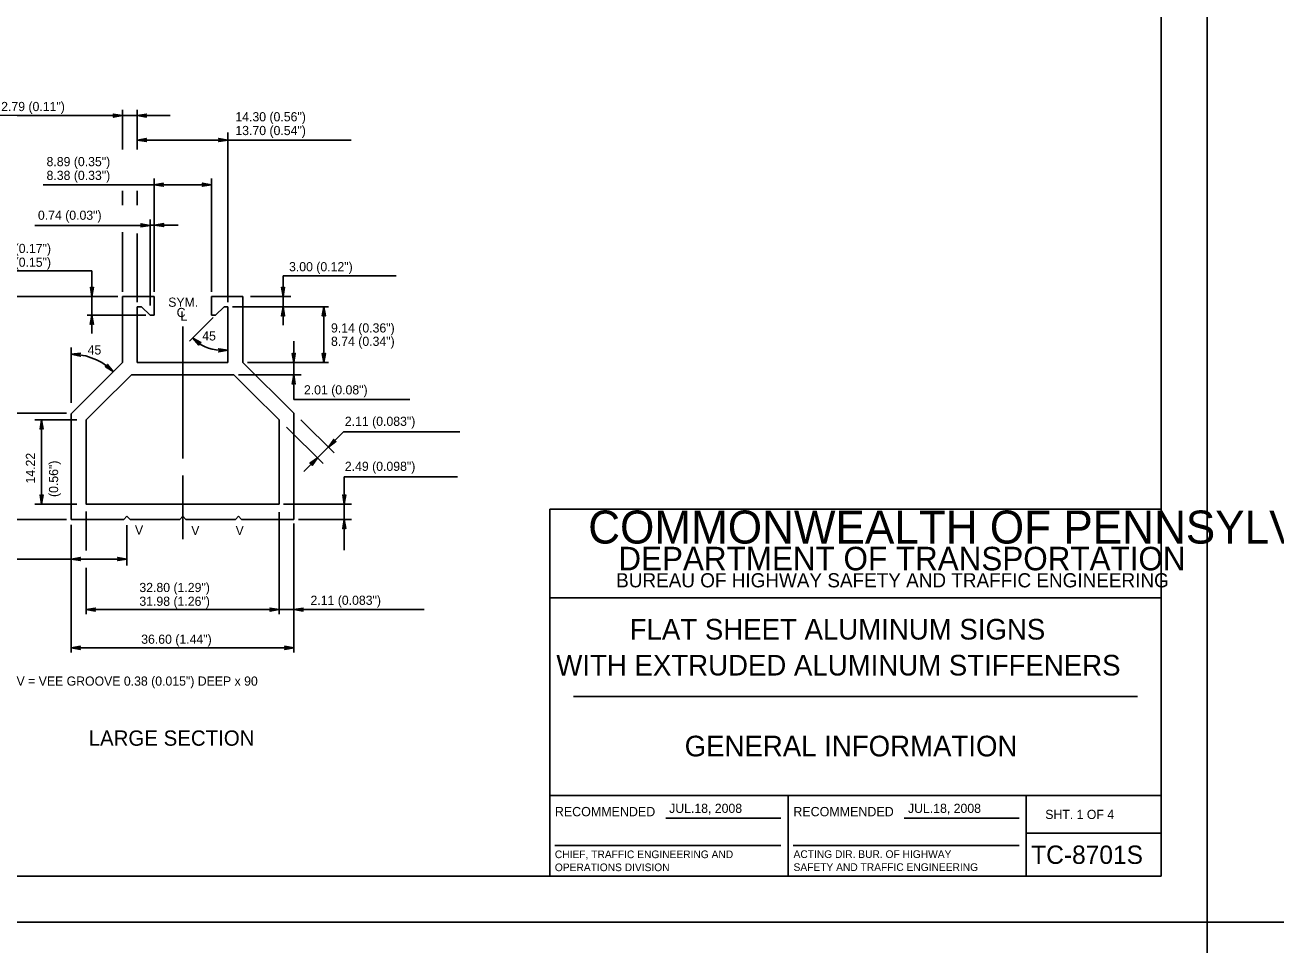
# Model space of a CAD drawing. Extents: x 650495 to 652241, y 298458 to 299646.
# Drawn here: x 650949.7 to 651358.9, y 299044.1 to 299344.9 of the extents above; entities that cross this region are included whole.
import ezdxf

# ---------------------------------------------------------------- set-up
doc = ezdxf.new("R2010")
doc.units = 0
for name, color, linetype in [('1', 7, 'Continuous'), ('2', 7, 'Continuous'), ('3', 7, 'Continuous'), ('Default', 7, 'Continuous'), ('PLT-BNDY', 7, 'Continuous')]:
    doc.layers.add(name, color=color, linetype=linetype)

# ---------------------------------------------------------------- blocks, each defined once
blk = doc.blocks.new('RARROW')
at = {"layer": '3'}
blk.add_lwpolyline([(-2.2695, 0.285), (-2.184875, 0.12075), (0, 0), (-2.2695, 0.285), (-2.38575, 0.384625), (0, 0), (-2.183125, -0.108), (-2.262875, -0.2705), (0, 0), (-2.38575, -0.379125), (-2.262875, -0.2705)], dxfattribs=at)

msp = doc.modelspace()

# ---------------------------------------------------------------- linework, layer by layer
at = {"layer": '1'}
for p, q in [((651321.31, 299066.63), (651321.31, 299630.63)), ((651121.31, 299066.63), (651121.31, 299186.63)), ((651121.31, 299186.63), (651321.31, 299186.63)), ((651321.31, 299157.63), (651121.31, 299157.63)), ((651129.06, 299125.31), (651313.56, 299125.31)), ((651121.31, 299093), (651321.31, 299093)), ((651199.31, 299093), (651199.31, 299066.63)), ((651277.19, 299066.63), (651277.19, 299093)), ((651159.24, 299085.57), (651196.87, 299085.57)), ((651237.24, 299085.57), (651274.87, 299085.57)), ((651277.19, 299080.63), (651321.31, 299080.63)), ((651122.99, 299076.68), (651196.87, 299076.68)), ((651200.99, 299076.68), (651274.87, 299076.68)), ((651321.31, 299066.63), (650535.31, 299066.63)), ((650535.31, 299066.63), (651121.31, 299066.63))]:
    msp.add_line(p, q, dxfattribs=at)
at = {"layer": '2'}
for p, q in [((650981.53, 299304.15), (650981.53, 299317.17)), ((650986.41, 299304.15), (650986.41, 299317.17)), ((650939.78, 299315.27), (650981.53, 299315.27)), ((650981.53, 299315.27), (650997.19, 299315.27)), ((651016.03, 299254.27), (651016.03, 299309.76)), ((650986.41, 299307.28), (651056.34, 299307.28)), ((650955.6, 299292.67), (651010.66, 299292.67)), ((650991.91, 299257.65), (650991.91, 299294.72)), ((651010.66, 299257.65), (651010.66, 299294.72)), ((650981.53, 299285.96), (650981.53, 299290.68)), ((650986.41, 299285.96), (650986.41, 299290.68)), ((650952.91, 299279.38), (650990.57, 299279.38)), ((650990.66, 299253.19), (650990.66, 299281.35)), ((650990.66, 299279.48), (650999.82, 299279.48)), ((650981.53, 299257.65), (650981.53, 299277.21)), ((650986.41, 299254.27), (650986.41, 299276.76)), ((650935.67, 299264.51), (650971.55, 299264.51)), ((650971.55, 299264.51), (650971.55, 299256.15)), ((651034.07, 299262.9), (651034.07, 299256.15)), ((651034.07, 299262.9), (651071.04, 299262.9)), ((650980.03, 299256.15), (650930.42, 299256.15)), ((650971.55, 299244.02), (650971.55, 299256.15)), ((650981.53, 299234.52), (650981.53, 299256.15)), ((650981.53, 299256.15), (650991.91, 299256.15)), ((650991.91, 299250.02), (650991.91, 299256.15)), ((651010.66, 299256.15), (651020.91, 299256.15)), ((651010.66, 299250.02), (651010.66, 299256.15)), ((651020.91, 299256.15), (651020.91, 299234.52)), ((651023.39, 299256.15), (651036.63, 299256.15)), ((651034.07, 299246.77), (651034.07, 299256.15)), ((650986.41, 299252.77), (650986.41, 299234.52)), ((650987.78, 299252.77), (650986.41, 299252.77)), ((650987.78, 299252.77), (650990.66, 299250.02)), ((651014.78, 299252.77), (651012.04, 299250.02)), ((651014.78, 299252.77), (651016.03, 299252.77)), ((651016.03, 299252.77), (651016.03, 299234.52)), ((651017.53, 299252.77), (651048.98, 299252.77)), ((651047.42, 299252.77), (651047.42, 299234.52)), ((650989.16, 299250.02), (650970.05, 299250.02)), ((650990.66, 299250.02), (650991.91, 299250.02)), ((651001.28, 299203.15), (651001.28, 299246.34)), ((651011.26, 299249.24), (651003.54, 299241.5)), ((651010.66, 299250.02), (651012.04, 299250.02)), ((650964.78, 299221.31), (650964.78, 299239.4)), ((651013.4, 299238.53), (651016.03, 299238.53)), ((651037.58, 299241.55), (651037.58, 299234.52)), ((650964.78, 299217.77), (650981.53, 299234.52)), ((650986.41, 299234.52), (650999.16, 299234.52)), ((651001.28, 299234.52), (651007.78, 299234.52)), ((651007.78, 299234.52), (651016.03, 299234.52)), ((651020.91, 299234.52), (651037.66, 299218.02)), ((651022.41, 299234.52), (651048.98, 299234.52)), ((651037.58, 299234.52), (651037.58, 299222.4)), ((651019.53, 299230.52), (651039.96, 299230.52)), ((651037.58, 299222.4), (651075.56, 299222.4)), ((650963.28, 299218.03), (650937.68, 299218.03)), ((650964.78, 299183.27), (650964.78, 299217.77)), ((651037.66, 299218.02), (651037.66, 299183.27)), ((650952.95, 299215.77), (650966.6, 299215.77)), ((650955.1, 299215.77), (650955.1, 299188.27)), ((651035.2, 299213.38), (651047.2, 299201.57)), ((651039.89, 299215.81), (651050.84, 299205.03)), ((651045.37, 299203.36), (651053.91, 299211.9)), ((651053.91, 299211.9), (651091.88, 299211.9)), ((651040.91, 299198.9), (651045.37, 299203.36)), ((651001.28, 299176.77), (651001.28, 299197.65)), ((651054.09, 299197.15), (651091.1, 299197.15)), ((651054.09, 299197.15), (651054.09, 299188.27)), ((650952.95, 299188.27), (650966.6, 299188.27)), ((650969.66, 299185.85), (650969.66, 299173.05)), ((651032.78, 299185.62), (651032.78, 299152.27)), ((651034.28, 299188.27), (651056.47, 299188.27)), ((651054.09, 299188.27), (651054.09, 299173.21)), ((650963.28, 299183.27), (650930.42, 299183.27)), ((650982.03, 299183.27), (650964.78, 299183.27)), ((650964.78, 299181.46), (650964.78, 299139.77)), ((650983.03, 299184.27), (650982.03, 299183.27)), ((650984.03, 299183.27), (650983.03, 299184.27)), ((650983.03, 299181.37), (650983.03, 299168.17)), ((651000.28, 299183.27), (650984.03, 299183.27)), ((651000.28, 299183.27), (651001.28, 299184.27)), ((651001.28, 299184.27), (651000.28, 299183.27)), ((651002.28, 299183.27), (651001.28, 299184.27)), ((651018.53, 299183.27), (651002.28, 299183.27)), ((651018.53, 299183.27), (651019.53, 299184.27)), ((651019.53, 299184.27), (651018.53, 299183.27)), ((651019.53, 299184.27), (651020.53, 299183.27)), ((651020.53, 299183.27), (651019.53, 299184.27)), ((651037.66, 299183.27), (651020.53, 299183.27)), ((651037.66, 299181.93), (651037.66, 299139.77)), ((651039.16, 299183.27), (651056.47, 299183.27)), ((650926.56, 299170.3), (650983.03, 299170.3)), ((650969.66, 299167.44), (650969.66, 299152.27)), ((650969.66, 299153.77), (651032.78, 299153.77)), ((651080.25, 299153.77), (651032.78, 299153.77)), ((650964.78, 299141.27), (651037.66, 299141.27))]:
    msp.add_line(p, q, dxfattribs=at)
for points in [[(650999.16, 299234.52), (651001.28, 299234.52)], [(650984.53, 299230.52), (650973.78, 299219.9)], [(650999.16, 299230.52), (650984.53, 299230.52)], [(651001.28, 299230.52), (650999.16, 299230.52)], [(651007.78, 299230.52), (651001.28, 299230.52)], [(651018.03, 299230.52), (651007.78, 299230.52)], [(651023.78, 299224.77), (651018.03, 299230.52)], [(651032.78, 299200.15), (651032.78, 299215.77), (651023.78, 299224.77)], [(650973.78, 299219.9), (650969.66, 299215.77), (650969.66, 299188.27), (650973.78, 299188.27)], [(651007.78, 299188.27), (651032.78, 299188.27), (651032.78, 299200.15)], [(650973.78, 299188.27), (651001.28, 299188.27)], [(651001.28, 299188.27), (651005.91, 299188.27)], [(651005.91, 299188.27), (651007.78, 299188.27)]]:
    msp.add_lwpolyline(points, dxfattribs=at)
for centre, radius, start, end in [((651014, 299251.58), 13.06, 223.8098, 267.3752), ((650964.78, 299217.77), 19.5, 45, 90)]:
    msp.add_arc(centre, radius, start, end, dxfattribs=at)
at = {"layer": 'PLT-BNDY'}
for points in [[(650495.31, 299645.63), (651336.31, 299645.63), (651336.31, 299051.63), (650495.31, 299051.63)], [(651336.31, 299645.63), (652177.31, 299645.63), (652177.31, 299051.63), (651336.31, 299051.63)], [(650495.31, 299051.63), (651336.31, 299051.63), (651336.31, 298457.63), (650495.31, 298457.63)], [(651336.31, 299051.63), (652177.31, 299051.63), (652177.31, 298457.63), (651336.31, 298457.63)]]:
    msp.add_lwpolyline(points, close=True, dxfattribs=at)

# ---------------------------------------------------------------- block references
at = {"layer": '2', "xscale": 1.2574347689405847, "yscale": 1.3092961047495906}
for p in [(650981.53, 299315.27), (651016.03, 299307.28), (651010.66, 299292.67), (650990.57, 299279.38), (651016.03, 299238.53), (650983.03, 299170.3), (651032.78, 299153.77), (651037.66, 299141.27)]:
    msp.add_blockref('RARROW', p, dxfattribs=at)
at = {"layer": '2'}
for p, xscale, yscale, rotation in [((650986.41, 299315.27), 1.2574347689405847, 1.3092961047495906, 180), ((650986.41, 299307.28), 1.2574347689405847, 1.3092961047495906, 180), ((650991.91, 299292.67), 1.2574347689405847, 1.3092961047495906, 180), ((650992.09, 299279.48), 1.2574347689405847, 1.3092961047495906, 180), ((650971.55, 299256.15), 1.2574347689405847, 1.3092961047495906, -90.00000000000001), ((651034.07, 299256.15), 1.2574347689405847, 1.3092961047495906, -90.00000000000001), ((651034.07, 299252.77), 1.2574347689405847, 1.3092961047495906, 89.99999999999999), ((651047.42, 299252.77), 1.2574347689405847, 1.3092961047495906, 89.99999999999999), ((650971.55, 299250.02), 1.2574347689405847, 1.3092961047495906, 89.99999999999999), ((651004.57, 299242.54), 1.2574347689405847, 1.3092961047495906, 140.9194989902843), ((650964.78, 299237.27), 1.2574347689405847, 1.3092961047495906, 176.80414646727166), ((650978.57, 299231.56), 1.2574347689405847, 1.3092961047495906, -40.89957129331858), ((651037.58, 299234.52), 1.2574347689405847, 1.3092961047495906, -90.00000000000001), ((651047.42, 299234.52), 1.2574347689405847, 1.3092961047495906, -90.00000000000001), ((651037.58, 299230.52), 1.2574347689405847, 1.3092961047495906, 89.99999999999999), ((650955.1, 299215.77), 1.2574347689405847, 1.3092961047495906, 89.99999999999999), ((651048.93, 299206.89), 1.2574347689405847, 1.3092961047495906, -134.02087905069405), ((651045.37, 299203.36), 1.2574347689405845, 1.3092961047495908, 44.7961575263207), ((650955.1, 299188.27), 1.2574347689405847, 1.3092961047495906, -90.00000000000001), ((651054.09, 299188.27), 1.2574347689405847, 1.3092961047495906, -90.00000000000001), ((651054.09, 299183.27), 1.2574347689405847, 1.3092961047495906, 89.99999999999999), ((650964.78, 299170.3), 1.2574347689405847, 1.3092961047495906, 180), ((650969.66, 299153.77), 1.2574347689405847, 1.3092961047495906, 180), ((651037.66, 299153.77), 1.2574347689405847, 1.3092961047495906, 180), ((650964.78, 299141.27), 1.2574347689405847, 1.3092961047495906, 180)]:
    msp.add_blockref('RARROW', p, dxfattribs=dict(at, xscale=xscale, yscale=yscale, rotation=rotation))

# ---------------------------------------------------------------- texts
at = {"layer": '1'}
for s, height, p in [('COMMONWEALTH OF PENNSYLVANIA', 10.7828, (651133.9, 299175.36)), ('DEPARTMENT OF TRANSPORTATION', 7.6837, (651143.76, 299166.61)), ('BUREAU OF HIGHWAY SAFETY AND TRAFFIC ENGINEERING', 4.6253, (651143.04, 299161.04)), ('FLAT SHEET ALUMINUM SIGNS', 6.75, (651147.47, 299143.97)), ('WITH EXTRUDED ALUMINUM STIFFENERS', 6.75, (651123.47, 299132.22)), ('GENERAL INFORMATION', 6.75, (651165.45, 299105.78)), ('RECOMMENDED', 3.048, (651122.99, 299086.2)), ('RECOMMENDED', 3.048, (651200.99, 299086.2)), ('SHT. 1 OF 4', 3, (651283.4, 299085.31)), ('CHIEF, TRAFFIC ENGINEERING AND', 2.5, (651122.99, 299072.51)), ('TC-8701S', 6, (651278.79, 299070.63)), ('OPERATIONS DIVISION', 2.5, (651122.99, 299068.26))]:
    msp.add_text(s, height=height, dxfattribs=at).set_placement(p)
at = {"layer": '2'}
for s, height, p in [('2.79 (0.11")', 3, (650941.89, 299316.74)), ('14.30 (0.56")', 3, (651018.49, 299313.39)), ('13.70 (0.54")', 3, (651018.49, 299308.89)), ('8.89 (0.35")', 3, (650956.73, 299298.73)), ('8.38 (0.33")', 3, (650956.73, 299294.23)), ('0.74 (0.03")', 3, (650953.91, 299281.2)), ('4.17 (0.17")', 3, (650937.37, 299270.34)), ('3.81 (0.15")', 3, (650937.37, 299265.84)), ('3.00 (0.12")', 3, (651036.04, 299264.37)), ('SYM.', 3, (650996.53, 299252.77)), ('C', 3, (650999.28, 299249.4)), ('L', 3, (651000.53, 299248.27)), ('9.14 (0.36")', 3, (651049.77, 299244.35)), ('45', 3, (651007.65, 299241.75)), ('8.74 (0.34")', 3, (651049.77, 299239.98)), ('45', 3, (650970.16, 299237.15)), ('2.01 (0.08")', 3, (651040.92, 299224.11)), ('2.11 (0.083")', 3, (651054.3, 299213.83)), ('2.49 (0.098")', 3, (651054.3, 299199.11)), ('V', 3, (650985.65, 299178.27)), ('V', 3, (651004.06, 299178.15)), ('V', 3, (651018.57, 299178.15)), ('32.80 (1.29")', 3, (650987.09, 299159.5)), ('31.98 (1.26")', 3, (650987.09, 299155)), ('2.11 (0.083")', 3, (651043.06, 299155.32)), ('36.60 (1.44")', 3, (650987.69, 299142.59)), ('V = VEE GROOVE 0.38 (0.015") DEEP x 90', 3, (650946.91, 299128.9)), ('LARGE SECTION', 5, (650970.5, 299109.26)), ('JUL.18, 2008', 3, (651160.37, 299087.3))]:
    msp.add_text(s, height=height, dxfattribs=at).set_placement(p)
for s, rotation, p in [('14.22 ', 90, (650952.96, 299194.98)), (' (0.56") ', 90, (650960.52, 299189.46)), ('JUL.18, 2008', 360, (651238.5, 299087.3))]:
    msp.add_text(s, height=3, rotation=rotation, dxfattribs=at).set_placement(p)
at = {"layer": 'Default'}
for s, p in [('ACTING DIR. BUR. OF HIGHWAY', (651201.06, 299072.57)), ('SAFETY AND TRAFFIC ENGINEERING', (651201.06, 299068.32))]:
    msp.add_text(s, height=2.5, dxfattribs=at).set_placement(p)

doc.saveas('drawing.dxf')
